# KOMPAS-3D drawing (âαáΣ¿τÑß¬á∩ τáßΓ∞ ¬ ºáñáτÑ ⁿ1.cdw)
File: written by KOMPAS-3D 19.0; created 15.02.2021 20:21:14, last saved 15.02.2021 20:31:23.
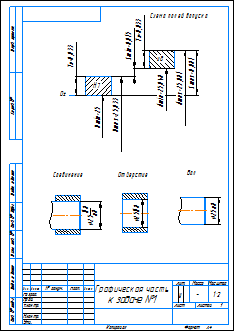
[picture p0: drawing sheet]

Sheet 1: A4, portrait

Document properties: Автор: Юрий; Полное имя файла: C:\Users\Юрий\Desktop\метрология сироп\Графическая часть к задаче №1.cdw

Title block, sheet 1: Наименование: Графическая часть / к задаче №1; Количество листов документа: 1; Форматы листов документа: A4; Литера: у

Views: Вид 1
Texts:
  Схема полей допуска
  Вал
  Отверстие
  Соединение
Dimensions and other numbers on the sheet: 81; 15; 25; 1:2; 1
